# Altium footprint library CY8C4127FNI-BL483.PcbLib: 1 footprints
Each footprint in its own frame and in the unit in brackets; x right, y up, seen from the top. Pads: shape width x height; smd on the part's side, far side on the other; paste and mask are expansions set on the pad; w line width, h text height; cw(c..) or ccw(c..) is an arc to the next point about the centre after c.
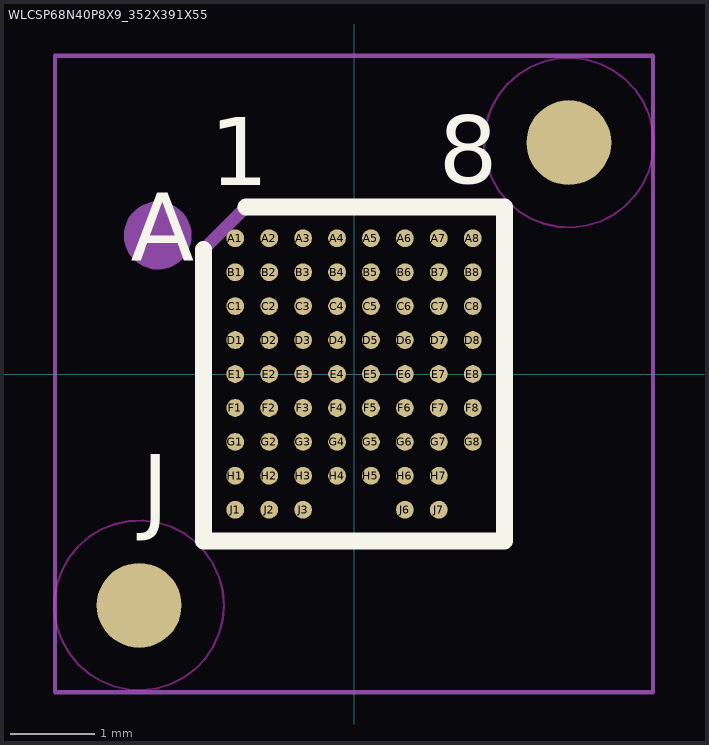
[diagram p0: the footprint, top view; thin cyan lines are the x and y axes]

## WLCSP68N40P8X9_352X391X55 [mm]
height 0.55
pads (70):
  round 0.21 smd mask+0: A1(-1.4,1.6) A2(-1,1.6) A3(-0.6,1.6) A4(-0.2,1.6) A5(0.2,1.6) A6(0.6,1.6) A7(1,1.6) A8(1.4,1.6) B1(-1.4,1.2) B2(-1,1.2) B3(-0.6,1.2) B4(-0.2,1.2) B5(0.2,1.2) B6(0.6,1.2) B7(1,1.2) B8(1.4,1.2) C1(-1.4,0.8) C2(-1,0.8) C3(-0.6,0.8) C4(-0.2,0.8) C5(0.2,0.8) C6(0.6,0.8) C7(1,0.8) C8(1.4,0.8) D1(-1.4,0.4) D2(-1,0.4) D3(-0.6,0.4) D4(-0.2,0.4) D5(0.2,0.4) D6(0.6,0.4) D7(1,0.4) D8(1.4,0.4) E1(-1.4,0) E2(-1,0) E3(-0.6,0) E4(-0.2,0) E5(0.2,0) E6(0.6,0) E7(1,0) E8(1.4,0) F1(-1.4,-0.4) F2(-1,-0.4) F3(-0.6,-0.4) F4(-0.2,-0.4) F5(0.2,-0.4) F6(0.6,-0.4) F7(1,-0.4) F8(1.4,-0.4) G1(-1.4,-0.8) G2(-1,-0.8) G3(-0.6,-0.8) G4(-0.2,-0.8) G5(0.2,-0.8) G6(0.6,-0.8) G7(1,-0.8) G8(1.4,-0.8) H1(-1.4,-1.2) H2(-1,-1.2) H3(-0.6,-1.2) H4(-0.2,-1.2) H5(0.2,-1.2) H6(0.6,-1.2) H7(1,-1.2) J1(-1.4,-1.6) J2(-1,-1.6) J3(-0.6,-1.6) J6(0.6,-1.6) J7(1,-1.6)
  round 1 smd mask+0.5: ""(-2.532,-2.727) ""(2.532,2.727)
Top Layer keep-out:
  circle w0.025: c2.532,2.727 r1
  circle w0.025: c-2.532,-2.727 r1
Top Overlay:
  lines w0.2: -1.773,1.468 -1.773,-1.967 1.773,-1.967 1.773,1.967 -1.272,1.967
  text "1" at -1.7,2.224 h0.8
  text ".Designator" at -2.75,4 h0.8
  text "A" at -2.633,1.333 h0.8
  text "J" at -2.5,-1.75 h0.8
  text "8" at 1,2.25 h0.8
Mechanical 13:
  circle w0.4: c-2.313,1.632 r0.2
  lines w0.15: -1.773,-1.967 -1.773,1.468 -1.272,1.967 1.773,1.967 1.773,-1.967 -1.773,-1.967
  text ".Designator" at -2.75,-0.25 h0.8
Mechanical 14:
  text "WLCSP68N40P8X9_352X391X55" at -9.25,5.5 h0.8
  text "C21" at -0.75,-4.75 h0.8
  text "C100M200K200" at -4.25,-6 h0.8
Mechanical 15:
  lines w0.05: -3.525,-3.75 -3.525,3.75 3.525,3.75 3.525,-3.75 -3.525,-3.75
3D body: height 0.55, standoff 0, extent -1.773,-1.968 1.773,1.968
